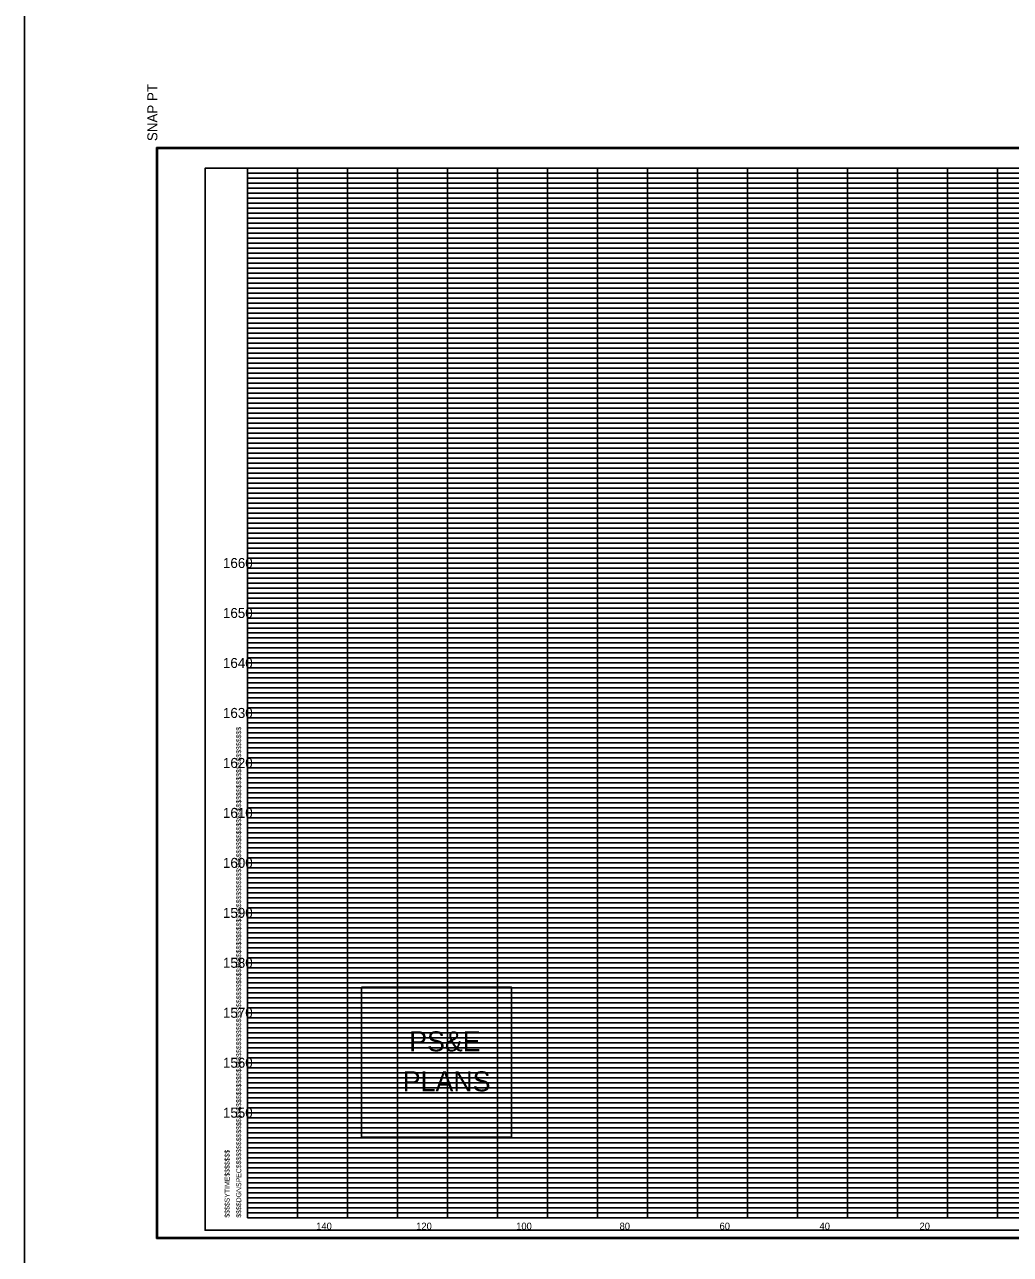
# Model space of a CAD drawing. Extents: x 955 to 1375, y 1248 to 3657.
# Drawn here: x 955.4 to 1152.6, y 2612.7 to 2858.7 of the extents above; entities that cross this region are included whole.
import ezdxf

# ---------------------------------------------------------------- set-up
doc = ezdxf.new("R2010")
doc.units = 0
for name, color, linetype in [('DESIGN - SHEET - Corner Text', 7, 'Continuous'), ('DESIGN - SHEET - Light Grid', 7, 'Continuous'), ('DESIGN - SHEET - Linework', 7, 'Continuous'), ('DESIGN - SHEET - Plot Shape', 7, 'Continuous'), ('DESIGN - TYPICAL - Text', 7, 'Continuous'), ('DESIGN - UTILITIES - Cable (Overhead) with Text', 7, 'Continuous'), ('SURVEY - NON-TRANSPORTATION - Features Text', 7, 'Continuous')]:
    doc.layers.add(name, color=color, linetype=linetype)

# ---------------------------------------------------------------- blocks, each defined once
blk = doc.blocks.new('XSTSHT')
at = {"layer": 'DESIGN - SHEET - Light Grid'}
for p, q in [((0, 20.9), (8, 20.9)), ((0, 20.8), (8, 20.8)), ((0, 20.7), (8, 20.7)), ((8, 20.9), (16, 20.9)), ((8, 20.8), (16, 20.8)), ((8, 20.7), (16, 20.7)), ((0, 20.6), (8, 20.6)), ((0, 20.5), (8, 20.5)), ((8, 20.6), (16, 20.6)), ((8, 20.5), (16, 20.5)), ((0, 20.4), (8, 20.4)), ((0, 20.3), (8, 20.3)), ((0, 20.2), (8, 20.2)), ((8, 20.4), (16, 20.4)), ((8, 20.3), (16, 20.3)), ((8, 20.2), (16, 20.2)), ((0, 20.1), (8, 20.1)), ((8, 20.1), (16, 20.1)), ((0, 19.9), (8, 19.9)), ((0, 19.8), (8, 19.8)), ((0, 19.7), (8, 19.7)), ((8, 19.9), (16, 19.9)), ((8, 19.8), (16, 19.8)), ((8, 19.7), (16, 19.7)), ((0, 19.6), (8, 19.6)), ((0, 19.5), (8, 19.5)), ((8, 19.6), (16, 19.6)), ((8, 19.5), (16, 19.5)), ((0, 19.4), (8, 19.4)), ((0, 19.3), (8, 19.3)), ((0, 19.2), (8, 19.2)), ((8, 19.4), (16, 19.4)), ((8, 19.3), (16, 19.3)), ((8, 19.2), (16, 19.2)), ((0, 19.1), (8, 19.1)), ((8, 19.1), (16, 19.1)), ((0, 18.9), (8, 18.9)), ((0, 18.8), (8, 18.8)), ((8, 18.9), (16, 18.9)), ((8, 18.8), (16, 18.8)), ((0, 18.7), (8, 18.7)), ((0, 18.6), (8, 18.6)), ((0, 18.5), (8, 18.5)), ((8, 18.7), (16, 18.7)), ((8, 18.6), (16, 18.6)), ((8, 18.5), (16, 18.5)), ((0, 18.4), (8, 18.4)), ((0, 18.3), (8, 18.3)), ((8, 18.4), (16, 18.4)), ((8, 18.3), (16, 18.3)), ((0, 18.2), (8, 18.2)), ((0, 18.1), (8, 18.1)), ((8, 18.2), (16, 18.2)), ((8, 18.1), (16, 18.1)), ((0, 17.9), (8, 17.9)), ((0, 17.8), (8, 17.8)), ((8, 17.9), (16, 17.9)), ((8, 17.8), (16, 17.8)), ((0, 17.7), (8, 17.7)), ((0, 17.6), (8, 17.6)), ((0, 17.5), (8, 17.5)), ((8, 17.7), (16, 17.7)), ((8, 17.6), (16, 17.6)), ((8, 17.5), (16, 17.5)), ((0, 17.4), (8, 17.4)), ((0, 17.3), (8, 17.3)), ((8, 17.4), (16, 17.4)), ((8, 17.3), (16, 17.3)), ((0, 17.2), (8, 17.2)), ((0, 17.1), (8, 17.1)), ((8, 17.2), (16, 17.2)), ((8, 17.1), (16, 17.1)), ((0, 16.9), (8, 16.9)), ((0, 16.8), (8, 16.8)), ((8, 16.9), (16, 16.9)), ((8, 16.8), (16, 16.8)), ((0, 16.7), (8, 16.7)), ((0, 16.6), (8, 16.6)), ((0, 16.5), (8, 16.5)), ((8, 16.7), (16, 16.7)), ((8, 16.6), (16, 16.6)), ((8, 16.5), (16, 16.5)), ((0, 16.4), (8, 16.4)), ((0, 16.3), (8, 16.3)), ((8, 16.4), (16, 16.4)), ((8, 16.3), (16, 16.3)), ((0, 16.2), (8, 16.2)), ((0, 16.1), (8, 16.1)), ((8, 16.2), (16, 16.2)), ((8, 16.1), (16, 16.1)), ((0, 15.9), (8, 15.9)), ((0, 15.8), (8, 15.8)), ((8, 15.9), (16, 15.9)), ((8, 15.8), (16, 15.8)), ((0, 15.7), (8, 15.7)), ((0, 15.6), (8, 15.6)), ((8, 15.7), (16, 15.7)), ((8, 15.6), (16, 15.6)), ((0, 15.5), (8, 15.5)), ((0, 15.4), (8, 15.4)), ((0, 15.3), (8, 15.3)), ((8, 15.5), (16, 15.5)), ((8, 15.4), (16, 15.4)), ((8, 15.3), (16, 15.3)), ((0, 15.2), (8, 15.2)), ((0, 15.1), (8, 15.1)), ((8, 15.2), (16, 15.2)), ((8, 15.1), (16, 15.1)), ((0, 14.9), (8, 14.9)), ((0, 14.8), (8, 14.8)), ((8, 14.9), (16, 14.9)), ((8, 14.8), (16, 14.8)), ((0, 14.7), (8, 14.7)), ((0, 14.6), (8, 14.6)), ((8, 14.7), (16, 14.7)), ((8, 14.6), (16, 14.6)), ((0, 14.5), (8, 14.5)), ((0, 14.4), (8, 14.4)), ((0, 14.3), (8, 14.3)), ((8, 14.5), (16, 14.5)), ((8, 14.4), (16, 14.4)), ((8, 14.3), (16, 14.3)), ((0, 14.2), (8, 14.2)), ((0, 14.1), (8, 14.1)), ((8, 14.2), (16, 14.2)), ((8, 14.1), (16, 14.1)), ((0, 13.9), (8, 13.9)), ((0, 13.8), (8, 13.8)), ((8, 13.9), (16, 13.9)), ((8, 13.8), (16, 13.8)), ((0, 13.7), (8, 13.7)), ((0, 13.6), (8, 13.6)), ((8, 13.7), (16, 13.7)), ((8, 13.6), (16, 13.6)), ((0, 13.5), (8, 13.5)), ((0, 13.4), (8, 13.4)), ((0, 13.3), (8, 13.3)), ((8, 13.5), (16, 13.5)), ((8, 13.4), (16, 13.4)), ((8, 13.3), (16, 13.3)), ((0, 13.2), (8, 13.2)), ((0, 13.1), (8, 13.1)), ((8, 13.2), (16, 13.2)), ((8, 13.1), (16, 13.1)), ((0, 12.9), (8, 12.9)), ((0, 12.8), (8, 12.8)), ((8, 12.9), (16, 12.9)), ((8, 12.8), (16, 12.8)), ((0, 12.7), (8, 12.7)), ((0, 12.6), (8, 12.6)), ((8, 12.7), (16, 12.7)), ((8, 12.6), (16, 12.6)), ((0, 12.5), (8, 12.5)), ((0, 12.4), (8, 12.4)), ((8, 12.5), (16, 12.5)), ((8, 12.4), (16, 12.4)), ((0, 12.3), (8, 12.3)), ((0, 12.2), (8, 12.2)), ((0, 12.1), (8, 12.1)), ((8, 12.3), (16, 12.3)), ((8, 12.2), (16, 12.2)), ((8, 12.1), (16, 12.1)), ((0, 11.9), (8, 11.9)), ((8, 11.9), (16, 11.9)), ((0, 11.8), (8, 11.8)), ((0, 11.7), (8, 11.7)), ((0, 11.6), (8, 11.6)), ((8, 11.8), (16, 11.8)), ((8, 11.7), (16, 11.7)), ((8, 11.6), (16, 11.6)), ((0, 11.5), (8, 11.5)), ((0, 11.4), (8, 11.4)), ((8, 11.5), (16, 11.5)), ((8, 11.4), (16, 11.4)), ((0, 11.3), (8, 11.3)), ((0, 11.2), (8, 11.2)), ((0, 11.1), (8, 11.1)), ((8, 11.3), (16, 11.3)), ((8, 11.2), (16, 11.2)), ((8, 11.1), (16, 11.1)), ((0, 10.9), (8, 10.9)), ((8, 10.9), (16, 10.9)), ((0, 10.8), (8, 10.8)), ((0, 10.7), (8, 10.7)), ((0, 10.6), (8, 10.6)), ((8, 10.8), (16, 10.8)), ((8, 10.7), (16, 10.7)), ((8, 10.6), (16, 10.6)), ((0, 10.5), (8, 10.5)), ((0, 10.4), (8, 10.4)), ((8, 10.5), (16, 10.5)), ((8, 10.4), (16, 10.4)), ((0, 10.3), (8, 10.3)), ((0, 10.2), (8, 10.2)), ((0, 10.1), (8, 10.1)), ((8, 10.3), (16, 10.3)), ((8, 10.2), (16, 10.2)), ((8, 10.1), (16, 10.1)), ((0, 9.9), (8, 9.9)), ((8, 9.9), (16, 9.9)), ((0, 9.8), (8, 9.8)), ((0, 9.7), (8, 9.7)), ((0, 9.6), (8, 9.6)), ((8, 9.8), (16, 9.8)), ((8, 9.7), (16, 9.7)), ((8, 9.6), (16, 9.6)), ((0, 9.5), (8, 9.5)), ((0, 9.4), (8, 9.4)), ((8, 9.5), (16, 9.5)), ((8, 9.4), (16, 9.4)), ((0, 9.3), (8, 9.3)), ((0, 9.2), (8, 9.2)), ((8, 9.3), (16, 9.3)), ((8, 9.2), (16, 9.2)), ((0, 9.1), (8, 9.1)), ((0, 8.9), (8, 8.9)), ((8, 9.1), (16, 9.1)), ((8, 8.9), (16, 8.9)), ((0, 8.8), (8, 8.8)), ((0, 8.7), (8, 8.7)), ((8, 8.8), (16, 8.8)), ((8, 8.7), (16, 8.7)), ((0, 8.6), (8, 8.6)), ((0, 8.5), (8, 8.5)), ((0, 8.4), (8, 8.4)), ((8, 8.6), (16, 8.6)), ((8, 8.5), (16, 8.5)), ((8, 8.4), (16, 8.4)), ((0, 8.3), (8, 8.3)), ((0, 8.2), (8, 8.2)), ((8, 8.3), (16, 8.3)), ((8, 8.2), (16, 8.2)), ((0, 8.1), (8, 8.1)), ((0, 7.9), (8, 7.9)), ((8, 8.1), (16, 8.1)), ((8, 7.9), (16, 7.9)), ((0, 7.8), (8, 7.8)), ((0, 7.7), (8, 7.7)), ((8, 7.8), (16, 7.8)), ((8, 7.7), (16, 7.7)), ((0, 7.6), (8, 7.6)), ((0, 7.5), (8, 7.5)), ((0, 7.4), (8, 7.4)), ((8, 7.6), (16, 7.6)), ((8, 7.5), (16, 7.5)), ((8, 7.4), (16, 7.4)), ((0, 7.3), (8, 7.3)), ((0, 7.2), (8, 7.2)), ((8, 7.3), (16, 7.3)), ((8, 7.2), (16, 7.2)), ((0, 7.1), (8, 7.1)), ((0, 6.9), (8, 6.9)), ((8, 7.1), (16, 7.1)), ((8, 6.9), (16, 6.9)), ((0, 6.8), (8, 6.8)), ((0, 6.7), (8, 6.7)), ((8, 6.8), (16, 6.8)), ((8, 6.7), (16, 6.7)), ((0, 6.6), (8, 6.6)), ((0, 6.5), (8, 6.5)), ((0, 6.4), (8, 6.4)), ((8, 6.6), (16, 6.6)), ((8, 6.5), (16, 6.5)), ((8, 6.4), (16, 6.4)), ((0, 6.3), (8, 6.3)), ((0, 6.2), (8, 6.2)), ((8, 6.3), (16, 6.3)), ((8, 6.2), (16, 6.2)), ((0, 6.1), (8, 6.1)), ((8, 6.1), (16, 6.1)), ((0, 5.9), (8, 5.9)), ((0, 5.8), (8, 5.8)), ((0, 5.7), (8, 5.7)), ((8, 5.9), (16, 5.9)), ((8, 5.8), (16, 5.8)), ((8, 5.7), (16, 5.7)), ((0, 5.6), (8, 5.6)), ((0, 5.5), (8, 5.5)), ((8, 5.6), (16, 5.6)), ((8, 5.5), (16, 5.5)), ((0, 5.4), (8, 5.4)), ((0, 5.3), (8, 5.3)), ((0, 5.2), (8, 5.2)), ((8, 5.4), (16, 5.4)), ((8, 5.3), (16, 5.3)), ((8, 5.2), (16, 5.2)), ((0, 5.1), (8, 5.1)), ((8, 5.1), (16, 5.1)), ((0, 4.9), (8, 4.9)), ((0, 4.8), (8, 4.8)), ((0, 4.7), (8, 4.7)), ((8, 4.9), (16, 4.9)), ((8, 4.8), (16, 4.8)), ((8, 4.7), (16, 4.7)), ((0, 4.6), (8, 4.6)), ((0, 4.5), (8, 4.5)), ((8, 4.6), (16, 4.6)), ((8, 4.5), (16, 4.5)), ((0, 4.4), (8, 4.4)), ((0, 4.3), (8, 4.3)), ((0, 4.2), (8, 4.2)), ((8, 4.4), (16, 4.4)), ((8, 4.3), (16, 4.3)), ((8, 4.2), (16, 4.2)), ((0, 4.1), (8, 4.1)), ((8, 4.1), (16, 4.1)), ((0, 3.9), (8, 3.9)), ((0, 3.8), (8, 3.8)), ((0, 3.7), (8, 3.7)), ((8, 3.9), (16, 3.9)), ((8, 3.8), (16, 3.8)), ((8, 3.7), (16, 3.7)), ((0, 3.6), (8, 3.6)), ((0, 3.5), (8, 3.5)), ((8, 3.6), (16, 3.6)), ((8, 3.5), (16, 3.5)), ((0, 3.4), (8, 3.4)), ((0, 3.3), (8, 3.3)), ((0, 3.2), (8, 3.2)), ((8, 3.4), (16, 3.4)), ((8, 3.3), (16, 3.3)), ((8, 3.2), (16, 3.2)), ((0, 3.1), (8, 3.1)), ((8, 3.1), (16, 3.1)), ((0, 2.9), (8, 2.9)), ((0, 2.8), (8, 2.8)), ((8, 2.9), (16, 2.9)), ((8, 2.8), (16, 2.8)), ((0, 2.7), (8, 2.7)), ((0, 2.6), (8, 2.6)), ((0, 2.5), (8, 2.5)), ((8, 2.7), (16, 2.7)), ((8, 2.6), (16, 2.6)), ((8, 2.5), (16, 2.5)), ((0, 2.4), (8, 2.4)), ((0, 2.3), (8, 2.3)), ((8, 2.4), (16, 2.4)), ((8, 2.3), (16, 2.3)), ((0, 2.2), (8, 2.2)), ((0, 2.1), (8, 2.1)), ((8, 2.2), (16, 2.2)), ((8, 2.1), (16, 2.1)), ((0, 1.9), (8, 1.9)), ((0, 1.8), (8, 1.8)), ((8, 1.9), (16, 1.9)), ((8, 1.8), (16, 1.8)), ((0, 1.7), (8, 1.7)), ((0, 1.6), (8, 1.6)), ((0, 1.5), (8, 1.5)), ((8, 1.7), (16, 1.7)), ((8, 1.6), (16, 1.6)), ((8, 1.5), (16, 1.5)), ((0, 1.4), (8, 1.4)), ((0, 1.3), (8, 1.3)), ((8, 1.4), (16, 1.4)), ((8, 1.3), (16, 1.3)), ((0, 1.2), (8, 1.2)), ((0, 1.1), (8, 1.1)), ((8, 1.2), (16, 1.2)), ((8, 1.1), (16, 1.1)), ((0, 0.9), (8, 0.9)), ((0, 0.8), (8, 0.8)), ((8, 0.9), (16, 0.9)), ((8, 0.8), (16, 0.8)), ((0, 0.7), (8, 0.7)), ((0, 0.6), (8, 0.6)), ((0, 0.5), (8, 0.5)), ((8, 0.7), (16, 0.7)), ((8, 0.6), (16, 0.6)), ((8, 0.5), (16, 0.5)), ((0, 0.4), (8, 0.4)), ((0, 0.3), (8, 0.3)), ((8, 0.4), (16, 0.4)), ((8, 0.3), (16, 0.3)), ((0, 0.2), (8, 0.2)), ((0, 0.1), (8, 0.1)), ((8, 0.2), (16, 0.2)), ((8, 0.1), (16, 0.1))]:
    blk.add_line(p, q, dxfattribs=at)
at = {"layer": 'DESIGN - SHEET - Linework'}
for p, q in [((-1.823, -0.414), (-1.823, 21.414)), ((-1.823, 21.414), (32.217, 21.414)), ((1, 0), (1, 21)), ((2, 0), (2, 21)), ((3, 0), (3, 21)), ((4, 0), (4, 21)), ((5, 0), (5, 21)), ((6, 0), (6, 21)), ((7, 0), (7, 21)), ((8, 0), (8, 21)), ((9, 0), (9, 21)), ((10, 0), (10, 21)), ((11, 0), (11, 21)), ((12, 0), (12, 21)), ((13, 0), (13, 21)), ((14, 0), (14, 21)), ((15, 0), (15, 21)), ((0, 20), (28, 20)), ((0, 19), (32, 19)), ((0, 18), (32, 18)), ((0, 17), (32, 17)), ((0, 16), (32, 16)), ((0, 15), (32, 15)), ((0, 14), (32, 14)), ((0, 13), (32, 13)), ((0, 12), (32, 12)), ((0, 11), (32, 11)), ((0, 10), (32, 10)), ((0, 9), (32, 9)), ((0, 8), (32, 8)), ((0, 7), (32, 7)), ((0, 6), (32, 6)), ((0, 5), (32, 5)), ((0, 4), (32, 4)), ((0, 3), (32, 3)), ((0, 2), (32, 2)), ((0, 1), (32, 1)), ((-1.823, -0.414), (32.217, -0.414))]:
    blk.add_line(p, q, dxfattribs=at)
blk.add_lwpolyline([(0, 21), (0, 0), (32, 0), (32, 21), (0, 21)], dxfattribs=at)
at = {"layer": 'DESIGN - SHEET - Plot Shape'}
for points in [[(-1.803, 21.394), (32.197, 21.394), (32.197, -0.394), (-1.803, -0.394)], [(-0.85, 21), (32, 21), (32, -0.25), (-0.85, -0.25)]]:
    blk.add_lwpolyline(points, close=True, dxfattribs=at)
at = {"layer": 'DESIGN - SHEET - Corner Text'}
for s, height, p in [('  SNAP PT', 0.2, (-1.803, 21.394)), ('$$$$DGNSPEC$$$$$$$$$$$$$$$$$$$$$$$$$$$$$$$$$$$$$$$$$$$$$$$$$$$$$$$$$$$$$$$$$$$$$$$$$$$$$$$$$$$$$$$$$$$$$$$$$$$$$$$$$$$$$$$$$$$', 0.100002, (-0.126, 0)), ('$$$$SYTIME$$$$$$$', 0.1, (-0.358, 0))]:
    blk.add_text(s, height=height, rotation=90, dxfattribs=at).set_placement(p)

msp = doc.modelspace()

# ---------------------------------------------------------------- linework, layer by layer
at = {"layer": 'DESIGN - SHEET - Corner Text'}
msp.add_lwpolyline([(1022.82, 2666.1), (1022.82, 2636.1), (1052.82, 2636.1), (1052.82, 2666.1)], close=True, dxfattribs=at)
at = {"layer": 'DESIGN - SHEET - Plot Shape'}
msp.add_lwpolyline([(991.5, 2617.5), (1320, 2617.5), (1320, 2830), (991.5, 2830)], close=True, dxfattribs=at)
at = {"layer": 'SURVEY - NON-TRANSPORTATION - Features Text'}
msp.add_lwpolyline([(955.41, 1505.76), (1344.98, 1505.76), (1344.98, 3398.01), (955.41, 3398.01)], close=True, dxfattribs=at)

# ---------------------------------------------------------------- block references
at = {"layer": 'DESIGN - UTILITIES - Cable (Overhead) with Text', "xscale": 10, "yscale": 10}
msp.add_blockref('XSTSHT', (1000, 2620), dxfattribs=at)

# ---------------------------------------------------------------- texts
at = {"layer": 'DESIGN - SHEET - Corner Text'}
for s, p in [('PS&E', (1032.34, 2653.28)), ('PLANS', (1031.06, 2645.28))]:
    msp.add_text(s, height=4, dxfattribs=at).set_placement(p)
at = {"layer": 'DESIGN - TYPICAL - Text'}
for s, height, p in [('     1660     ', 2, (991.37, 2750)), ('     1650     ', 2, (991.37, 2740)), ('     1640     ', 2, (991.37, 2730)), ('     1630     ', 2, (991.37, 2720)), ('     1620     ', 2, (991.37, 2710)), ('     1610     ', 2, (991.37, 2700)), ('     1600     ', 2, (991.37, 2690)), ('     1590     ', 2, (991.37, 2680)), ('     1580     ', 2, (991.37, 2670)), ('     1570     ', 2, (991.37, 2660)), ('     1560     ', 2, (991.37, 2650)), ('     1550     ', 2, (991.37, 2640)), ('     140     ', 1.4, (1011.14, 2617.6)), ('     120     ', 1.4, (1031.14, 2617.6)), ('     100     ', 1.4, (1051.14, 2617.6)), ('     80     ', 1.4, (1071.82, 2617.6)), ('     60     ', 1.4, (1091.82, 2617.6)), ('     40     ', 1.4, (1111.82, 2617.6)), ('     20     ', 1.4, (1131.82, 2617.6))]:
    msp.add_text(s, height=height, dxfattribs=at).set_placement(p)

doc.saveas('drawing.dxf')
